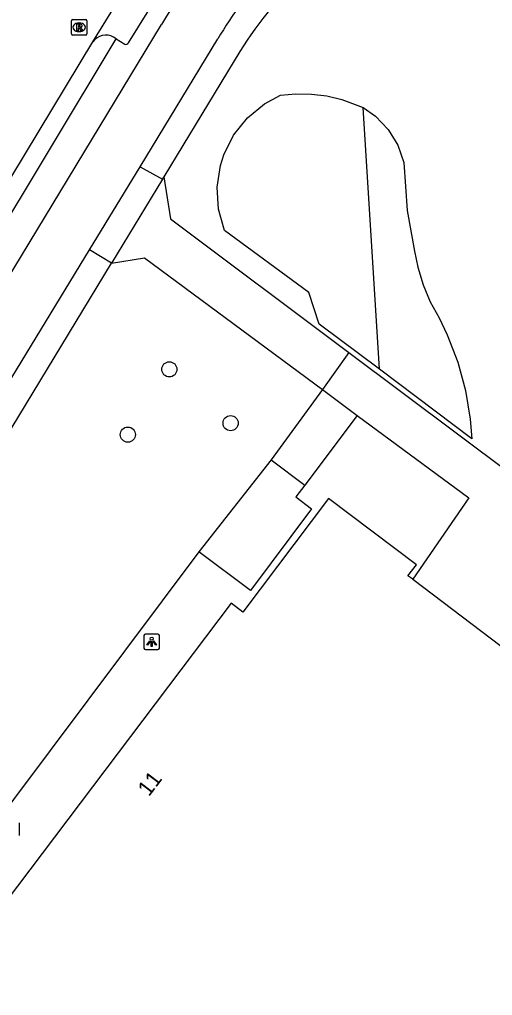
# Model space of a CAD drawing. Extents: x 160356 to 161355, y 381727 to 382845.
# Drawn here: x 161085.4 to 161115.9, y 382137.5 to 382200.4 of the extents above; entities that cross this region are included whole.
import ezdxf

# ---------------------------------------------------------------- set-up
doc = ezdxf.new("R2010")
doc.units = 0
for name, color, linetype in [('IMGEO_Boom', 7, 'Continuous'), ('IMGEO_Fietspad_gesloten', 7, 'Continuous'), ('IMGEO_Groenvoorziening', 7, 'Continuous'), ('IMGEO_Lichtpunt', 7, 'Continuous'), ('IMGEO_Pand', 7, 'Continuous'), ('IMGEO_Pand_nummerreeks', 7, 'Continuous'), ('IMGEO_Parkeervlak_open', 7, 'Continuous'), ('IMGEO_Rijbaan_lokaal_open', 7, 'Continuous'), ('IMGEO_Rioolput', 7, 'Continuous'), ('IMGEO_Voetpad_open', 7, 'Continuous')]:
    doc.layers.add(name, color=color, linetype=linetype)

msp = doc.modelspace()

# ---------------------------------------------------------------- linework, layer by layer
at = {"layer": 'IMGEO_Boom'}
for centre in [(161095.063, 382177.843), (161099.01, 382174.376), (161092.39, 382173.635)]:
    msp.add_circle(centre, 0.489, dxfattribs=at)
at = {"layer": 'IMGEO_Fietspad_gesloten'}
for points in [[(161036.885, 382104.942), (161037.001, 382105.126), (161044.262, 382117.085), (161072.545, 382163.708), (161094.564, 382200.063)], [(161093.18, 382190.895), (161098.193, 382199.139)], [(161089.928, 382185.548), (161093.18, 382190.895)], [(161040.022, 382103.393), (161049.862, 382119.664), (161056.078, 382129.917), (161089.928, 382185.548)]]:
    msp.add_lwpolyline(points, dxfattribs=at)
for centre, radius, start, end in [((161122.262, 382183.981), 32.028, 131.77368, 149.85973), ((161119.228, 382187.042), 24.265, 124.12478, 150.09651)]:
    msp.add_arc(centre, radius, start, end, dxfattribs=at)
at = {"layer": 'IMGEO_Groenvoorziening'}
for points in [[(161108.595, 382177.844), (161104.718, 382180.762), (161104.041, 382182.795), (161098.607, 382186.79), (161098.229, 382188.16), (161098.143, 382189.578), (161098.354, 382190.983), (161098.569, 382191.662), (161099.204, 382192.933), (161100.09, 382194.044), (161101.187, 382194.947), (161102.228, 382195.511), (161103.218, 382195.598), (161104.212, 382195.582), (161105.199, 382195.462), (161106.167, 382195.239), (161107.542, 382194.728)], [(161107.542, 382194.728), (161108.344, 382194.155), (161109.157, 382193.297), (161109.773, 382192.289), (161110.167, 382191.174), (161110.379, 382188.073), (161110.858, 382185.468), (161111.063, 382184.42), (161111.406, 382183.285), (161111.865, 382182.193), (161112.436, 382181.154), (161112.965, 382180.072), (161113.647, 382178.311), (161114.141, 382176.488), (161114.442, 382174.623), (161114.539, 382173.371), (161108.595, 382177.844)], [(161108.595, 382177.844), (161107.542, 382194.728)]]:
    msp.add_lwpolyline(points, dxfattribs=at)
at = {"layer": 'IMGEO_Lichtpunt'}
for p, q in [((161093.427, 382160.684), (161093.427, 382159.877)), ((161093.427, 382160.684), (161093.427, 382159.877)), ((161094.329, 382160.779), (161093.521, 382160.779)), ((161094.329, 382160.779), (161093.521, 382160.779)), ((161094.423, 382159.877), (161094.423, 382160.684)), ((161094.423, 382159.877), (161094.423, 382160.684)), ((161093.521, 382159.783), (161094.329, 382159.783)), ((161093.521, 382159.783), (161094.329, 382159.783)), ((161085.414, 382147.799), (161085.414, 382148.606)), ((161085.414, 382147.799), (161085.414, 382148.606))]:
    msp.add_line(p, q, dxfattribs=at)
for points in [[(161093.801, 382160.348), (161093.84, 382160.32), (161093.652, 382160.058), (161093.614, 382160.085), (161093.801, 382160.348)], [(161093.903, 382160.3), (161093.95, 382160.3), (161093.95, 382159.978), (161093.903, 382159.978), (161093.903, 382160.3)], [(161094.013, 382160.32), (161094.051, 382160.347), (161094.238, 382160.085), (161094.199, 382160.057), (161094.013, 382160.32)]]:
    msp.add_lwpolyline(points, dxfattribs=at)
msp.add_circle((161093.926, 382160.482), 0.0994, dxfattribs=at)
for centre, start, end in [((161093.521, 382160.684), 90, 180), ((161093.521, 382160.684), 90, 180), ((161094.329, 382160.684), 0, 90), ((161094.329, 382160.684), 0, 90), ((161093.521, 382159.877), 180, 270), ((161093.521, 382159.877), 180, 270), ((161094.329, 382159.877), 270, 0), ((161094.329, 382159.877), 270, 360)]:
    msp.add_arc(centre, 0.0946, start, end, dxfattribs=at)
at = {"layer": 'IMGEO_Pand'}
for points in [[(161110.736, 382164.311), (161110.433, 382164.541), (161110.972, 382165.239), (161105.316, 382169.518), (161099.802, 382162.195), (161099.037, 382162.772), (161083.609, 382142.34), (161084.351, 382141.78), (161079.433, 382135.265), (161079.013, 382134.714)], [(161110.736, 382164.311), (161124.623, 382153.783), (161128.045, 382151.189), (161131.707, 382156.067), (161139.208, 382150.436), (161129.553, 382137.625)]]:
    msp.add_lwpolyline(points, dxfattribs=at)
at = {"layer": 'IMGEO_Parkeervlak_open'}
for points in [[(161092.427, 382198.895), (161098.658, 382208.929), (161098.645, 382209.04)], [(161091.646, 382199.151), (161092.202, 382198.807)]]:
    msp.add_lwpolyline(points, dxfattribs=at)
msp.add_arc((161092.279, 382198.942), 0.155, 240.38455, 342.33749, dxfattribs=at)
at = {"layer": 'IMGEO_Rijbaan_lokaal_open'}
for points in [[(161090.133, 382198.954), (161097.529, 382210.923)], [(161082.246, 382185.913), (161090.133, 382198.954)]]:
    msp.add_lwpolyline(points, dxfattribs=at)
at = {"layer": 'IMGEO_Rioolput'}
for p, q in [((161088.751, 382199.464), (161088.751, 382200.316)), ((161088.826, 382200.39), (161089.678, 382200.39)), ((161089.239, 382200.17), (161089.264, 382200.17)), ((161089.752, 382200.316), (161089.752, 382199.464)), ((161089.678, 382199.39), (161088.826, 382199.39)), ((161089.262, 382199.61), (161089.237, 382199.61))]:
    msp.add_line(p, q, dxfattribs=at)
for points in [[(161088.751, 382199.464), (161088.751, 382200.316)], [(161088.826, 382200.39), (161089.678, 382200.39)], [(161089.34, 382200.088), (161089.088, 382200.09), (161089.088, 382199.69)], [(161089.088, 382199.69), (161089.212, 382199.69), (161089.212, 382199.852), (161089.223, 382199.852)], [(161089.266, 382200.009), (161089.212, 382200.009), (161089.212, 382199.928)], [(161089.212, 382199.928), (161089.264, 382199.928)], [(161089.27, 382199.823), (161089.341, 382199.69), (161089.481, 382199.69), (161089.416, 382199.816)], [(161089.752, 382200.316), (161089.752, 382199.464)], [(161089.678, 382199.39), (161088.826, 382199.39)]]:
    msp.add_lwpolyline(points, dxfattribs=at)
for centre, radius, start, end in [((161088.828, 382200.314), 0.0765, 91.55205, 178.44795), ((161088.828, 382200.314), 0.0765, 91.55205, 178.44795), ((161089.222, 382199.799), 0.0533, 26.02933, 88.69889), ((161089.248, 382200.117), 0.19, 274.7715, 282.96867), ((161089.272, 382199.913), 0.0964, 77.00612, 93.18647), ((161089.286, 382199.97), 0.0378, 276.66336, 79.67722), ((161089.339, 382199.978), 0.109, 350.36119, 89.41601), ((161089.337, 382199.978), 0.112, 277.58423, 350.98172), ((161089.321, 382199.763), 0.108, 29.51342, 73.79051), ((161089.676, 382200.314), 0.0765, 1.55205, 88.44795), ((161089.676, 382200.314), 0.0765, 1.55205, 88.44795), ((161088.828, 382199.466), 0.0765, 181.55205, 268.44795), ((161088.828, 382199.466), 0.0765, 181.55205, 268.44795), ((161089.676, 382199.466), 0.0765, 271.55205, 358.44795), ((161089.676, 382199.466), 0.0765, 271.55205, 358.44795)]:
    msp.add_arc(centre, radius, start, end, dxfattribs=at)
for centre, major_axis, ratio, start_param, end_param in [((161089.238, 382199.89), (-0.387, 0.002), 0.722429, 4.712389, 7.853982), ((161089.263, 382199.89), (-0.39, 0.002), 0.717154, 1.570796, 4.712389)]:
    msp.add_ellipse(centre, major_axis=major_axis, ratio=ratio, start_param=start_param, end_param=end_param, dxfattribs=at)
at = {"layer": 'IMGEO_Voetpad_open'}
for points in [[(161091.646, 382199.151), (161091.473, 382199.253)], [(161082.246, 382185.913), (161083.276, 382185.277), (161091.646, 382199.151)], [(161099.601, 382198.326), (161094.71, 382190.256)], [(161093.18, 382190.895), (161094.617, 382190.106)], [(161094.617, 382190.106), (161091.332, 382184.687)], [(161094.617, 382190.106), (161094.71, 382190.256)], [(161094.71, 382190.256), (161095.132, 382187.55), (161106.633, 382178.932)], [(161091.332, 382184.687), (161089.928, 382185.548)], [(161066.578, 382143.827), (161091.332, 382184.687)], [(161091.332, 382184.687), (161093.47, 382185.023), (161104.927, 382176.534)], [(161106.633, 382178.932), (161104.927, 382176.534)], [(161106.633, 382178.932), (161144.956, 382150.216), (161142.825, 382147.476)], [(161104.927, 382176.534), (161101.611, 382172.003)], [(161104.927, 382176.534), (161107.17, 382174.872)], [(161107.17, 382174.872), (161103.782, 382170.387)], [(161107.17, 382174.872), (161114.349, 382169.552), (161110.736, 382164.311)], [(161101.611, 382172.003), (161096.957, 382166.077)], [(161101.611, 382172.003), (161103.782, 382170.387)], [(161103.782, 382170.387), (161103.206, 382169.632), (161104.229, 382168.856), (161100.299, 382163.578), (161096.957, 382166.077)], [(161096.957, 382166.077), (161080.216, 382143.711)]]:
    msp.add_lwpolyline(points, dxfattribs=at)
for centre, radius, start, end in [((161118.488, 382186.749), 22.153, 130.61254, 148.49354), ((161090.97, 382198.357), 1.028, 60.68498, 144.47221)]:
    msp.add_arc(centre, radius, start, end, dxfattribs=at)

# ---------------------------------------------------------------- texts
at = {"layer": 'IMGEO_Pand_nummerreeks'}
msp.add_text('11', height=1, rotation=52.76368, dxfattribs=at).set_placement((161093.746, 382150.262))

doc.saveas('drawing.dxf')
